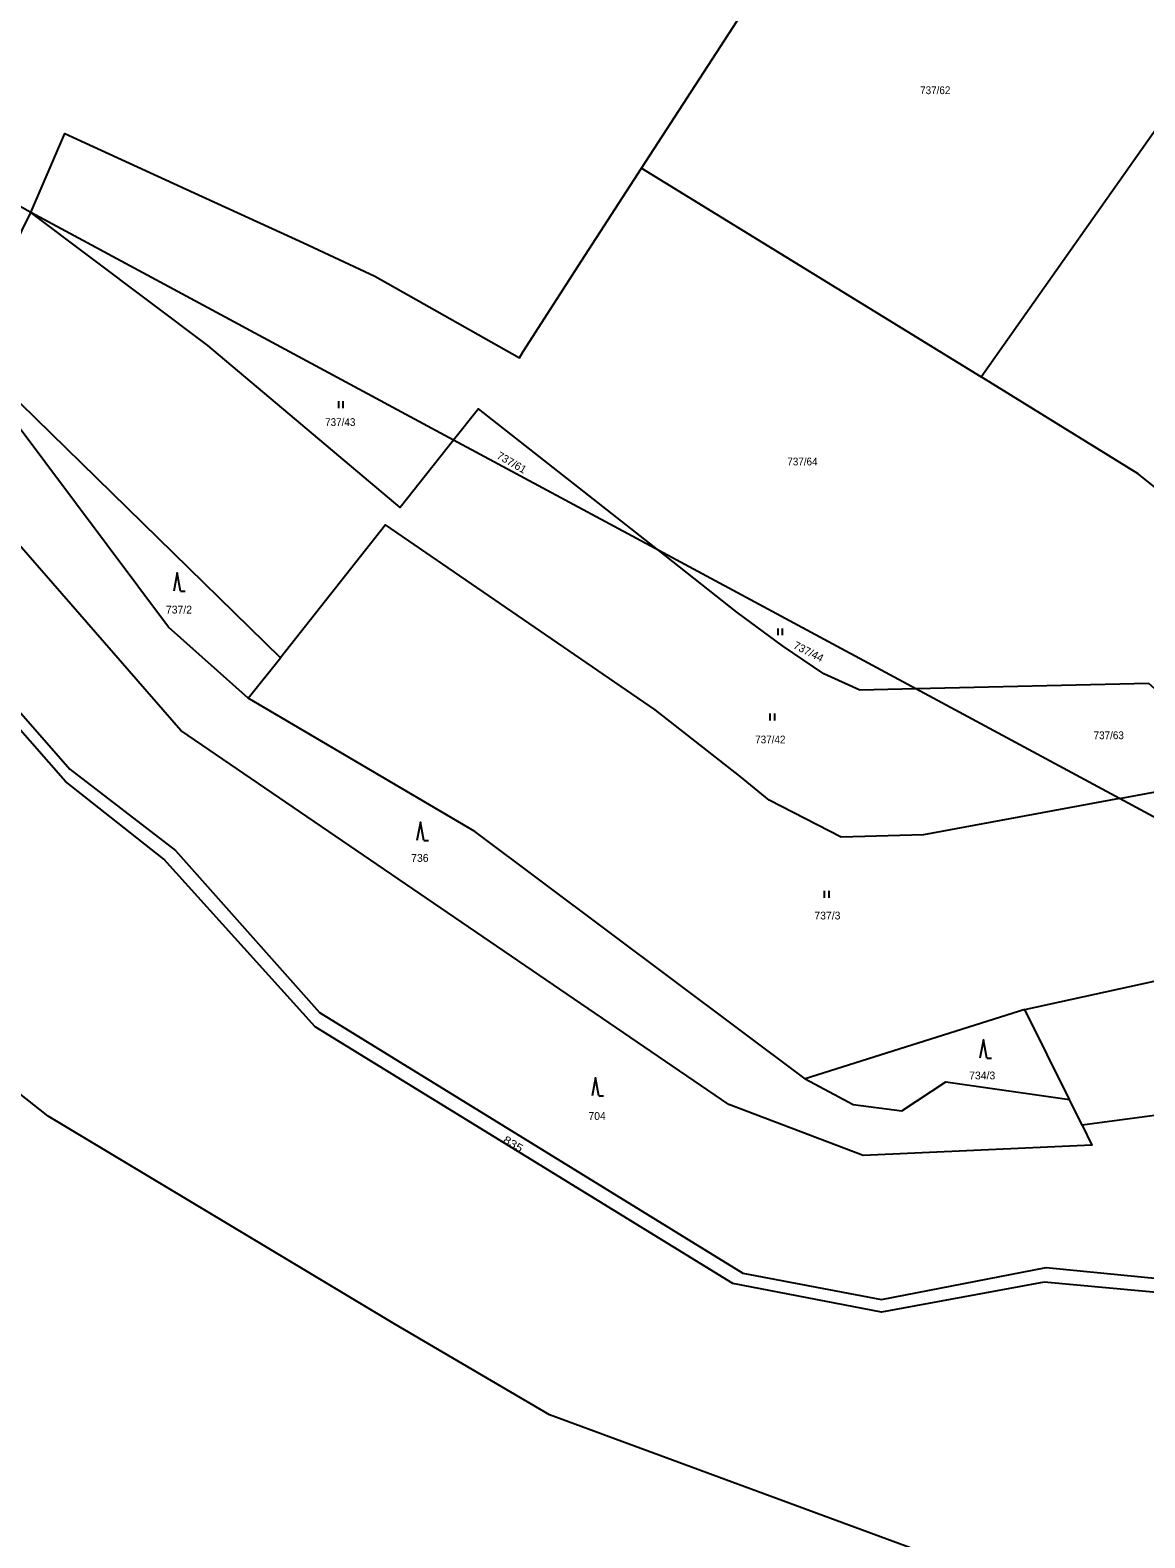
# Model space of a CAD drawing. Extents: x -687135 to -684370, y -1007309 to -1005782.
# Drawn here: x -686608.2 to -686364.9, y -1006769.6 to -1006440.4 of the extents above; entities that cross this region are included whole.
import ezdxf

# ---------------------------------------------------------------- set-up
doc = ezdxf.new("R2010")
doc.units = 0
doc.header["$LTSCALE"] = 0.68
doc.layers.add('1', color=7, linetype='Continuous', lineweight=25)
doc.layers.add('3', color=7, linetype='Continuous', lineweight=25)
doc.layers.add('2', color=7, linetype='Continuous')

msp = doc.modelspace()

# ---------------------------------------------------------------- linework, layer by layer
at = {"layer": '1'}
for p, q in [((-686515.83, -1006529.9), (-686608.08, -1006480.21)), ((-686471.01, -1006554.04), (-686515.83, -1006529.9)), ((-686414.94, -1006584.24), (-686471.01, -1006554.04)), ((-686370.47, -1006608.19), (-686414.94, -1006584.24)), ((-686378.58, -1006679.53), (-686381.38, -1006673.88))]:
    msp.add_line(p, q, dxfattribs=at)
for points in [[(-686474.82, -1006470.5), (-686451.25, -1006434.18), (-686445.31, -1006425.09), (-686418.85, -1006388.46)], [(-686474.82, -1006470.5), (-686400.67, -1006516.06), (-686338.16, -1006427.36)], [(-686984.76, -1006428.31), (-686969.57, -1006429.7), (-686934.19, -1006429.13), (-686907.35, -1006435.05), (-686851.6, -1006457.67), (-686817.92, -1006486.94), (-686781.69, -1006496.55), (-686760.9, -1006489.89), (-686724.99, -1006485.24), (-686692.9, -1006493.7), (-686661.95, -1006520.83), (-686640.73, -1006554.73), (-686599.57, -1006601.79), (-686576.51, -1006619.5), (-686545.07, -1006654.9), (-686452.7, -1006711.84), (-686422.4, -1006717.6), (-686386.45, -1006710.61), (-686333.13, -1006715.82), (-686262.62, -1006718.78), (-686241.47, -1006709.79), (-686203.86, -1006711.97)], [(-686624.03, -1006512.52), (-686608.08, -1006480.21), (-686691.95, -1006433.27)], [(-686608.08, -1006480.21), (-686600.67, -1006462.95), (-686572.47, -1006475.93), (-686548.6, -1006486.83), (-686532.97, -1006494.09), (-686501.42, -1006511.96), (-686500.63, -1006510.53), (-686487.91, -1006490.77), (-686474.82, -1006470.5)], [(-686378.58, -1006679.53), (-686376.49, -1006683.84), (-686426.43, -1006686.12), (-686455.76, -1006674.99), (-686575.36, -1006593.34), (-686634.73, -1006525.16), (-686705.53, -1006469.79)], [(-686515.83, -1006529.9), (-686527.45, -1006544.63), (-686569.46, -1006509.25), (-686608.08, -1006480.21)], [(-686560.65, -1006586.24), (-686578.06, -1006570.74), (-686611.76, -1006525.73), (-686613.68, -1006518.64), (-686624.03, -1006512.52)], [(-686350.38, -1006591.28), (-686362.33, -1006580), (-686349.27, -1006551.01), (-686366.38, -1006537.29), (-686400.67, -1006516.06)], [(-686560.65, -1006586.24), (-686553.58, -1006577.43), (-686613.68, -1006518.64)], [(-686471.01, -1006554.04), (-686510.41, -1006523.04), (-686515.83, -1006529.9)], [(-686370.47, -1006608.19), (-686413.21, -1006616.11), (-686431.24, -1006616.59), (-686446.91, -1006608.51), (-686453.32, -1006603.29), (-686471.83, -1006588.8), (-686530.7, -1006548.44), (-686553.58, -1006577.43)], [(-686414.94, -1006584.24), (-686427.16, -1006584.53), (-686435, -1006580.97), (-686444.02, -1006574.8), (-686453.98, -1006567.44), (-686471.01, -1006554.04)], [(-685878.5, -1006732.89), (-685928.73, -1006713.6), (-685975.55, -1006716.87), (-685988.08, -1006722.32), (-686011.25, -1006727.78), (-686034.41, -1006726.41), (-686082.84, -1006705.15), (-686115.81, -1006703.51), (-686202.12, -1006715.24), (-686241.64, -1006713.33), (-686262.35, -1006721.24), (-686330.66, -1006718.97), (-686386.9, -1006713.77), (-686422.4, -1006720.35), (-686454.83, -1006714.05), (-686546.04, -1006658.04), (-686579.08, -1006621.42), (-686600.54, -1006604.47), (-686642.63, -1006556.52)], [(-686370.47, -1006608.19), (-686339, -1006602.36), (-686352.33, -1006593.47), (-686364.06, -1006583.04), (-686414.94, -1006584.24)], [(-686439.07, -1006669.41), (-686511.18, -1006615.34), (-686560.65, -1006586.24)], [(-686310.84, -1006644.34), (-686311.36, -1006640.03), (-686370.47, -1006608.19)], [(-686604.28, -1006677.55), (-686637.15, -1006651.59), (-686615.61, -1006642.29)], [(-686391.1, -1006654.24), (-686360.59, -1006647.58), (-686318.67, -1006644.32), (-686310.84, -1006644.34)], [(-686381.38, -1006673.88), (-686391.1, -1006654.24), (-686439.07, -1006669.41)], [(-686439.07, -1006669.41), (-686428.58, -1006674.98), (-686417.96, -1006676.37), (-686408.35, -1006670.04), (-686381.38, -1006673.88)], [(-686322.66, -1006677.37), (-686339.37, -1006674.28), (-686378.58, -1006679.53)], [(-686494.84, -1006742.74), (-686528.64, -1006722.93), (-686604.28, -1006677.55)], [(-686377.61, -1006790.04), (-686384.13, -1006783.59), (-686494.84, -1006742.74)]]:
    msp.add_lwpolyline(points, dxfattribs=at)
at = {"layer": '3'}
for p, q in [((-686540.881, -1006522.9), (-686540.881, -1006521.4)), ((-686539.88, -1006522.9), (-686539.88, -1006521.4)), ((-686575.4, -1006562.9), (-686574.404, -1006562.9)), ((-686444.991, -1006572.53), (-686444.991, -1006571.03)), ((-686443.99, -1006572.53), (-686443.99, -1006571.03)), ((-686446.701, -1006591.14), (-686446.701, -1006589.64)), ((-686445.7, -1006591.14), (-686445.7, -1006589.64)), ((-686522.31, -1006617.35), (-686521.314, -1006617.35)), ((-686434.861, -1006629.85), (-686434.861, -1006628.35)), ((-686433.86, -1006629.85), (-686433.86, -1006628.35)), ((-686399.41, -1006664.84), (-686398.414, -1006664.84)), ((-686484.09, -1006673.13), (-686483.094, -1006673.13))]:
    msp.add_line(p, q, dxfattribs=at)
for points in [[(-686575.4, -1006562.9), (-686576.15, -1006558.9), (-686576.9, -1006562.9)], [(-686522.31, -1006617.35), (-686523.06, -1006613.35), (-686523.81, -1006617.35)], [(-686399.41, -1006664.84), (-686400.16, -1006660.84), (-686400.91, -1006664.84)], [(-686484.09, -1006673.13), (-686484.84, -1006669.13), (-686485.59, -1006673.13)]]:
    msp.add_lwpolyline(points, dxfattribs=at)

# ---------------------------------------------------------------- texts
at = {"layer": '2', "width": 0.95}
for s, p in [('737/62', (-686413.98, -1006454.35)), ('737/43', (-686543.85, -1006526.82)), ('737/64', (-686442.97, -1006535.429)), ('737/42', (-686449.98, -1006596.13)), ('737/63', (-686376.11, -1006595.21))]:
    msp.add_text(s, height=1.7, dxfattribs=at).set_placement(p)
at = {"layer": '2'}
for s, rotation, p in [('737/61', 330, (-686506.555, -1006533.786)), ('737/44', 333, (-686441.805, -1006575.277))]:
    msp.add_text(s, height=1.7, rotation=rotation, dxfattribs=at).set_placement(p)
for s, p in [('737/2', (-686578.6, -1006567.77)), ('736', (-686525.07, -1006622)), ('737/3', (-686437.06, -1006634.58)), ('734/3', (-686403.27, -1006669.5)), ('704', (-686486.38, -1006678.35))]:
    msp.add_text(s, height=1.7, dxfattribs=at).set_placement(p)
at = {"layer": '2', "width": 1.2}
msp.add_text('835', height=1.7, rotation=329, dxfattribs=at).set_placement((-686505.177, -1006683.158))

doc.saveas('drawing.dxf')
